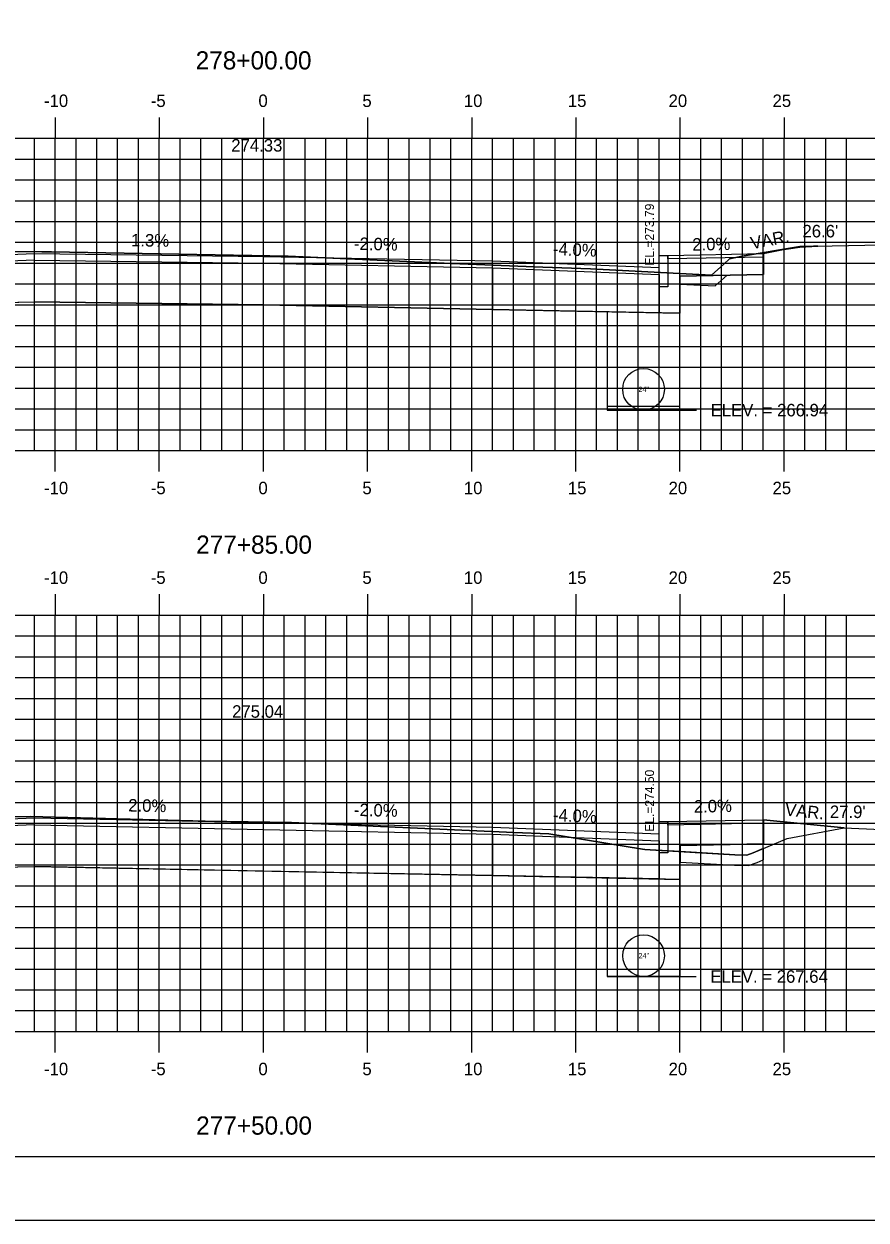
# Model space of a CAD drawing. Extents: x 854453 to 854623, y 366268 to 366378.
# Drawn here: x 854524.9 to 854565.4, y 366268.2 to 366325.6 of the extents above; entities that cross this region are included whole.
import ezdxf

# ---------------------------------------------------------------- set-up
doc = ezdxf.new("R2010")
doc.units = 0
for name, color, linetype in [('ANNOTATION', 7, 'Continuous'), ('BORDER', 7, 'Continuous'), ('D_Curb_Type_1_Rt', 7, 'Continuous'), ('D_Roadway_Centerline', 7, 'Continuous'), ('D_Roadway_Centerline_Text', 7, 'Continuous'), ('D_Roadway_Edge_Shoulder', 7, 'Continuous'), ('D_Roadway_Edge_TW', 7, 'Continuous'), ('D_Roadway_FinishedGrade', 7, 'Continuous'), ('D_Roadway_Sidewalks_Paved', 7, 'Continuous'), ('D_Roadway_SubGrade', 7, 'Continuous'), ('D_Text_Standard', 7, 'Continuous'), ('H_V ANNOTATION', 7, 'Continuous'), ('JUNK COM EXC', 7, 'Continuous'), ('JUNK FILL', 7, 'Continuous'), ('junk grubnfill', 7, 'Continuous'), ('junk strct exc', 7, 'Continuous'), ('MAJOR', 7, 'Continuous'), ('MINOR', 7, 'Continuous'), ('PDRAIN', 7, 'Continuous'), ('PLOT BOUNDARY', 7, 'Continuous'), ('S_Roadway_Centerline', 7, 'Continuous')]:
    doc.layers.add(name, color=color, linetype=linetype)

msp = doc.modelspace()

# ---------------------------------------------------------------- linework, layer by layer
at = {"layer": 'BORDER'}
msp.add_line((854461.439, 366271.236), (854621.439, 366271.236), dxfattribs=at)
at = {"layer": 'D_Curb_Type_1_Rt'}
for points in [[(854555.855, 366314.51), (854555.855, 366313.01), (854555.438, 366313.01), (854555.438, 366314.51)], [(854555.855, 366287.318), (854555.855, 366285.818), (854555.439, 366285.818), (854555.439, 366287.318)]]:
    msp.add_lwpolyline(points, close=True, dxfattribs=at)
at = {"layer": 'D_Roadway_Centerline'}
msp.add_lwpolyline([(854525.439, 366314.61), (854536.439, 366314.467), (854547.439, 366314.247)], dxfattribs=at)
at = {"layer": 'D_Roadway_Edge_Shoulder'}
msp.add_lwpolyline([(854517.439, 366314.29), (854525.439, 366314.61), (854536.439, 366314.467), (854547.439, 366314.247), (854555.434, 366313.927)], dxfattribs=at)
at = {"layer": 'D_Roadway_Edge_TW'}
msp.add_lwpolyline([(854517.439, 366287.174), (854525.439, 366287.494), (854547.439, 366287.054), (854555.434, 366286.734)], dxfattribs=at)
at = {"layer": 'D_Roadway_FinishedGrade'}
for p, q in [((854560.443, 366314.602), (854561.336, 366314.776)), ((854560.443, 366287.409), (854564.329, 366287.018))]:
    msp.add_line(p, q, dxfattribs=at)
msp.add_arc((854563.255, 366304.962), 10, 91.10922, 101.06432, dxfattribs=at)
at = {"layer": 'D_Roadway_Sidewalks_Paved'}
for points in [[(854555.855, 366314.51), (854560.443, 366314.602), (854560.443, 366314.435), (854555.855, 366314.344)], [(854555.855, 366287.317), (854560.443, 366287.409), (854560.443, 366287.242), (854555.855, 366287.151)]]:
    msp.add_lwpolyline(points, close=True, dxfattribs=at)
at = {"layer": 'D_Roadway_SubGrade'}
msp.add_line((854560.439, 366286.024), (854560.439, 366285.482), dxfattribs=at)
for points in [[(854560.443, 366314.435), (854560.443, 366313.602), (854556.439, 366313.522), (854556.439, 366311.733), (854555.439, 366311.753)], [(854556.439, 366313.136), (854558.125, 366313.047), (854558.712, 366313.567)], [(854555.442, 366284.561), (854556.442, 366284.541), (854556.442, 366286.163), (854560.444, 366286.242), (854560.444, 366287.242)], [(854556.442, 366285.373), (854559.06, 366285.219), (854559.733, 366285.207), (854560.14, 366285.357), (854560.439, 366285.482)]]:
    msp.add_lwpolyline(points, dxfattribs=at)
for points in [[(854525.439, 366314.276), (854517.439, 366313.956), (854517.439, 366312.116), (854525.439, 366312.276)], [(854525.439, 366312.276), (854525.439, 366314.276), (854536.439, 366314.133), (854547.439, 366313.913), (854547.439, 366311.913), (854536.439, 366312.133)], [(854547.439, 366313.913), (854555.439, 366313.593), (854555.439, 366311.753), (854547.439, 366311.913)], [(854525.439, 366287.161), (854517.439, 366286.841), (854517.439, 366285.001), (854525.439, 366285.161)], [(854525.439, 366285.161), (854525.439, 366287.161), (854536.439, 366286.941), (854547.439, 366286.721), (854547.439, 366284.721), (854536.439, 366284.941)], [(854547.439, 366286.721), (854555.438, 366286.401), (854555.438, 366284.561), (854547.439, 366284.721)]]:
    msp.add_lwpolyline(points, close=True, dxfattribs=at)
at = {"layer": 'D_Text_Standard'}
for points in [[(854556.439, 366307.081), (854556.552, 366307.081), (854557.232, 366307.081)], [(854556.442, 366279.876), (854556.536, 366279.876), (854557.216, 366279.876)]]:
    msp.add_lwpolyline(points, dxfattribs=at)
at = {"layer": 'JUNK COM EXC'}
for points in [[(854516.439, 366312.096), (854525.439, 366312.276), (854536.439, 366312.133), (854547.439, 366311.913), (854556.439, 366311.733), (854556.439, 366313.522), (854560.443, 366313.602), (854560.443, 366314.602), (854561.336, 366314.776), (854562.195, 366314.906), (854563.061, 366314.96), (854562.191, 366314.943), (854559.426, 366314.472), (854558.821, 366314.345), (854558.551, 366314.092), (854557.947, 366313.557), (854552.145, 366313.864), (854549.856, 366313.941), (854545.477, 366314.129), (854537.624, 366314.472), (854528.872, 366314.638), (854526.255, 366314.684), (854525.794, 366314.691), (854518.996, 366314.706)], [(854516.439, 366284.981), (854525.439, 366285.161), (854547.439, 366284.721), (854556.442, 366284.541), (854556.442, 366285.874), (854555.009, 366285.958), (854554.759, 366285.977), (854554.645, 366285.985), (854550.143, 366286.731), (854548.458, 366286.8), (854537.783, 366287.274), (854533.635, 366287.344), (854525.262, 366287.564), (854521.88, 366287.531)]]:
    msp.add_lwpolyline(points, dxfattribs=at)
at = {"layer": 'JUNK FILL'}
msp.add_lwpolyline([(854564.329, 366287.018), (854560.443, 366287.409), (854560.444, 366286.242), (854556.442, 366286.163), (854556.442, 366285.874), (854559.079, 366285.719), (854559.648, 366285.708), (854559.956, 366285.822), (854561.583, 366286.503)], close=True, dxfattribs=at)
at = {"layer": 'junk grubnfill'}
msp.add_lwpolyline([(854560.439, 366285.482), (854560.439, 366286.024), (854559.956, 366285.822), (854559.648, 366285.708), (854559.079, 366285.719), (854556.442, 366285.874), (854556.442, 366285.373), (854559.06, 366285.219), (854559.733, 366285.207), (854560.14, 366285.357), (854560.439, 366285.482)], dxfattribs=at)
at = {"layer": 'junk strct exc'}
for points in [[(854552.939, 366311.803), (854552.939, 366307.271), (854556.439, 366307.271), (854556.439, 366311.733)], [(854552.942, 366284.611), (854552.942, 366279.896), (854556.442, 366279.896), (854556.442, 366284.541)]]:
    msp.add_lwpolyline(points, close=True, dxfattribs=at)
at = {"layer": 'MAJOR'}
for p, q in [((854526.439, 366321.143), (854526.439, 366320.141)), ((854531.439, 366321.143), (854531.439, 366320.141)), ((854536.439, 366321.143), (854536.439, 366320.141)), ((854541.439, 366321.143), (854541.439, 366320.141)), ((854546.439, 366321.143), (854546.439, 366320.141)), ((854551.439, 366321.143), (854551.439, 366320.141)), ((854556.439, 366321.143), (854556.439, 366320.141)), ((854561.439, 366321.143), (854561.439, 366320.141)), ((854466.439, 366320.141), (854606.439, 366320.141)), ((854466.439, 366320.141), (854606.439, 366320.141)), ((854526.439, 366305.141), (854526.439, 366320.141)), ((854531.439, 366305.141), (854531.439, 366320.141)), ((854536.439, 366305.141), (854536.439, 366320.141)), ((854541.439, 366305.141), (854541.439, 366320.141)), ((854546.439, 366305.141), (854546.439, 366320.141)), ((854551.439, 366305.141), (854551.439, 366320.141)), ((854556.439, 366305.141), (854556.439, 366320.141)), ((854561.439, 366305.141), (854561.439, 366320.141)), ((854466.439, 366315.141), (854606.439, 366315.141)), ((854466.439, 366310.141), (854606.439, 366310.141)), ((854466.439, 366305.141), (854606.439, 366305.141)), ((854466.439, 366305.141), (854606.439, 366305.141)), ((854526.439, 366304.139), (854526.439, 366305.141)), ((854531.439, 366304.139), (854531.439, 366305.141)), ((854536.439, 366304.139), (854536.439, 366305.141)), ((854541.439, 366304.139), (854541.439, 366305.141)), ((854546.439, 366304.139), (854546.439, 366305.141)), ((854551.439, 366304.139), (854551.439, 366305.141)), ((854556.439, 366304.139), (854556.439, 366305.141)), ((854561.439, 366304.139), (854561.439, 366305.141)), ((854526.439, 366298.238), (854526.439, 366297.236)), ((854531.439, 366298.238), (854531.439, 366297.236)), ((854536.439, 366298.238), (854536.439, 366297.236)), ((854541.439, 366298.238), (854541.439, 366297.236)), ((854546.439, 366298.238), (854546.439, 366297.236)), ((854551.439, 366298.238), (854551.439, 366297.236)), ((854556.439, 366298.238), (854556.439, 366297.236)), ((854561.439, 366298.238), (854561.439, 366297.236)), ((854466.439, 366297.236), (854606.439, 366297.236)), ((854466.439, 366297.236), (854606.439, 366297.236)), ((854526.439, 366277.236), (854526.439, 366297.236)), ((854531.439, 366277.236), (854531.439, 366297.236)), ((854536.439, 366277.236), (854536.439, 366297.236)), ((854541.439, 366277.236), (854541.439, 366297.236)), ((854546.439, 366277.236), (854546.439, 366297.236)), ((854551.439, 366277.236), (854551.439, 366297.236)), ((854556.439, 366277.236), (854556.439, 366297.236)), ((854561.439, 366277.236), (854561.439, 366297.236)), ((854466.439, 366292.236), (854606.439, 366292.236)), ((854466.439, 366287.236), (854606.439, 366287.236)), ((854466.439, 366282.236), (854606.439, 366282.236)), ((854466.439, 366277.236), (854606.439, 366277.236)), ((854466.439, 366277.236), (854606.439, 366277.236)), ((854526.439, 366276.234), (854526.439, 366277.236)), ((854531.439, 366276.234), (854531.439, 366277.236)), ((854536.439, 366276.234), (854536.439, 366277.236)), ((854541.439, 366276.234), (854541.439, 366277.236)), ((854546.439, 366276.234), (854546.439, 366277.236)), ((854551.439, 366276.234), (854551.439, 366277.236)), ((854556.439, 366276.234), (854556.439, 366277.236)), ((854561.439, 366276.234), (854561.439, 366277.236))]:
    msp.add_line(p, q, dxfattribs=at)
at = {"layer": 'MINOR'}
for p, q in [((854525.439, 366305.141), (854525.439, 366320.141)), ((854527.439, 366305.141), (854527.439, 366320.141)), ((854528.439, 366305.141), (854528.439, 366320.141)), ((854529.439, 366305.141), (854529.439, 366320.141)), ((854530.439, 366305.141), (854530.439, 366320.141)), ((854532.439, 366305.141), (854532.439, 366320.141)), ((854533.439, 366305.141), (854533.439, 366320.141)), ((854534.439, 366305.141), (854534.439, 366320.141)), ((854535.439, 366305.141), (854535.439, 366320.141)), ((854537.439, 366305.141), (854537.439, 366320.141)), ((854538.439, 366305.141), (854538.439, 366320.141)), ((854539.439, 366305.141), (854539.439, 366320.141)), ((854540.439, 366305.141), (854540.439, 366320.141)), ((854542.439, 366305.141), (854542.439, 366320.141)), ((854543.439, 366305.141), (854543.439, 366320.141)), ((854544.439, 366305.141), (854544.439, 366320.141)), ((854545.439, 366305.141), (854545.439, 366320.141)), ((854547.439, 366305.141), (854547.439, 366320.141)), ((854548.439, 366305.141), (854548.439, 366320.141)), ((854549.439, 366305.141), (854549.439, 366320.141)), ((854550.439, 366305.141), (854550.439, 366320.141)), ((854552.439, 366305.141), (854552.439, 366320.141)), ((854553.439, 366305.141), (854553.439, 366320.141)), ((854554.439, 366305.141), (854554.439, 366320.141)), ((854555.439, 366305.141), (854555.439, 366320.141)), ((854557.439, 366305.141), (854557.439, 366320.141)), ((854558.439, 366305.141), (854558.439, 366320.141)), ((854559.439, 366305.141), (854559.439, 366320.141)), ((854560.439, 366305.141), (854560.439, 366320.141)), ((854562.439, 366305.141), (854562.439, 366320.141)), ((854563.439, 366305.141), (854563.439, 366320.141)), ((854564.439, 366305.141), (854564.439, 366320.141)), ((854466.439, 366319.141), (854606.439, 366319.141)), ((854466.439, 366318.141), (854606.439, 366318.141)), ((854466.439, 366317.141), (854606.439, 366317.141)), ((854466.439, 366316.141), (854606.439, 366316.141)), ((854466.439, 366314.141), (854606.439, 366314.141)), ((854466.439, 366313.141), (854606.439, 366313.141)), ((854466.439, 366312.141), (854606.439, 366312.141)), ((854466.439, 366311.141), (854606.439, 366311.141)), ((854466.439, 366309.141), (854606.439, 366309.141)), ((854466.439, 366308.141), (854606.439, 366308.141)), ((854466.439, 366307.141), (854606.439, 366307.141)), ((854466.439, 366306.141), (854606.439, 366306.141)), ((854525.439, 366277.236), (854525.439, 366297.236)), ((854527.439, 366277.236), (854527.439, 366297.236)), ((854528.439, 366277.236), (854528.439, 366297.236)), ((854529.439, 366277.236), (854529.439, 366297.236)), ((854530.439, 366277.236), (854530.439, 366297.236)), ((854532.439, 366277.236), (854532.439, 366297.236)), ((854533.439, 366277.236), (854533.439, 366297.236)), ((854534.439, 366277.236), (854534.439, 366297.236)), ((854535.439, 366277.236), (854535.439, 366297.236)), ((854537.439, 366277.236), (854537.439, 366297.236)), ((854538.439, 366277.236), (854538.439, 366297.236)), ((854539.439, 366277.236), (854539.439, 366297.236)), ((854540.439, 366277.236), (854540.439, 366297.236)), ((854542.439, 366277.236), (854542.439, 366297.236)), ((854543.439, 366277.236), (854543.439, 366297.236)), ((854544.439, 366277.236), (854544.439, 366297.236)), ((854545.439, 366277.236), (854545.439, 366297.236)), ((854547.439, 366277.236), (854547.439, 366297.236)), ((854548.439, 366277.236), (854548.439, 366297.236)), ((854549.439, 366277.236), (854549.439, 366297.236)), ((854550.439, 366277.236), (854550.439, 366297.236)), ((854552.439, 366277.236), (854552.439, 366297.236)), ((854553.439, 366277.236), (854553.439, 366297.236)), ((854554.439, 366277.236), (854554.439, 366297.236)), ((854555.439, 366277.236), (854555.439, 366297.236)), ((854557.439, 366277.236), (854557.439, 366297.236)), ((854558.439, 366277.236), (854558.439, 366297.236)), ((854559.439, 366277.236), (854559.439, 366297.236)), ((854560.439, 366277.236), (854560.439, 366297.236)), ((854562.439, 366277.236), (854562.439, 366297.236)), ((854563.439, 366277.236), (854563.439, 366297.236)), ((854564.439, 366277.236), (854564.439, 366297.236)), ((854466.439, 366296.236), (854606.439, 366296.236)), ((854466.439, 366295.236), (854606.439, 366295.236)), ((854466.439, 366294.236), (854606.439, 366294.236)), ((854466.439, 366293.236), (854606.439, 366293.236)), ((854466.439, 366291.236), (854606.439, 366291.236)), ((854466.439, 366290.236), (854606.439, 366290.236)), ((854466.439, 366289.236), (854606.439, 366289.236)), ((854466.439, 366288.236), (854606.439, 366288.236)), ((854466.439, 366286.236), (854606.439, 366286.236)), ((854466.439, 366285.236), (854606.439, 366285.236)), ((854466.439, 366284.236), (854606.439, 366284.236)), ((854466.439, 366283.236), (854606.439, 366283.236)), ((854466.439, 366281.236), (854606.439, 366281.236)), ((854466.439, 366280.236), (854606.439, 366280.236)), ((854466.439, 366279.236), (854606.439, 366279.236)), ((854466.439, 366278.236), (854606.439, 366278.236))]:
    msp.add_line(p, q, dxfattribs=at)
at = {"layer": 'PDRAIN'}
for points in [[(854552.939, 366311.803), (854552.939, 366307.081), (854556.439, 366307.081), (854556.439, 366311.733)], [(854552.942, 366284.611), (854552.942, 366279.876), (854556.442, 366279.876), (854556.442, 366284.541)]]:
    msp.add_lwpolyline(points, dxfattribs=at)
for centre in [(854554.689, 366308.081), (854554.692, 366280.876)]:
    msp.add_circle(centre, 1, dxfattribs=at)
at = {"layer": 'PLOT BOUNDARY'}
msp.add_lwpolyline([(854453.345, 366268.177), (854623.345, 366268.177), (854623.345, 366378.177), (854453.345, 366378.177)], close=True, dxfattribs=at)
at = {"layer": 'S_Roadway_Centerline'}
for points in [[(854518.996, 366314.706), (854525.794, 366314.691), (854526.255, 366314.684), (854528.872, 366314.638), (854537.624, 366314.472), (854545.477, 366314.129), (854549.856, 366313.941), (854552.145, 366313.864), (854557.947, 366313.557), (854558.551, 366314.092), (854558.821, 366314.345), (854559.426, 366314.472), (854562.191, 366314.943), (854567.654, 366315.049)], [(854521.88, 366287.531), (854525.262, 366287.564), (854533.635, 366287.344), (854537.783, 366287.274), (854548.458, 366286.8), (854550.143, 366286.731), (854554.645, 366285.985), (854554.759, 366285.977), (854555.009, 366285.958), (854559.079, 366285.719), (854559.648, 366285.708), (854559.956, 366285.822), (854561.583, 366286.503), (854564.329, 366287.018), (854567.532, 366286.879)]]:
    msp.add_lwpolyline(points, dxfattribs=at)

# ---------------------------------------------------------------- texts
at = {"layer": 'ANNOTATION'}
for s, rotation, p in [('1.3%', 359.2552, (854530.08, 366314.949)), ('VAR.', 11.06432, (854559.891, 366314.799)), ('-2.0%', 358.85424, (854540.782, 366314.78)), ('-4.0%', 357.70949, (854550.332, 366314.532)), ('2.0%', 1.14563, (854557.035, 366314.738)), ('2.0%', 358.85424, (854529.942, 366287.805)), ('-2.0%', 358.85424, (854540.782, 366287.588)), ('-4.0%', 357.70947, (854550.334, 366287.339)), ('2.0%', 1.14881, (854557.109, 366287.743)), ('VAR.', 354.25391, (854561.463, 366287.608))]:
    msp.add_text(s, height=0.6, rotation=rotation, dxfattribs=at).set_placement(p)
at = {"layer": 'D_Roadway_Centerline_Text'}
for s, p in [('274.33', (854534.895, 366319.499)), ('275.04', (854534.935, 366292.306))]:
    msp.add_text(s, height=0.6, dxfattribs=at).set_placement(p)
at = {"layer": 'D_Text_Standard'}
for s, p in [(' EL.=273.79', (854555.193, 366313.858)), (' EL.=274.50', (854555.193, 366286.666))]:
    msp.add_text(s, height=0.4335, rotation=90, dxfattribs=at).set_placement(p)
for s, p in [("26.6'", (854562.321, 366315.378)), ('ELEV. = 266.94', (854557.912, 366306.781)), ("27.9'", (854563.638, 366287.488)), ('ELEV. = 267.64', (854557.896, 366279.576))]:
    msp.add_text(s, height=0.6, dxfattribs=at).set_placement(p)
at = {"layer": 'H_V ANNOTATION'}
for s, height, p in [('278+00.00', 0.875, (854533.184, 366323.444)), ('-10', 0.6, (854525.903, 366321.641)), ('-5', 0.6, (854531.029, 366321.641)), ('0', 0.6, (854536.198, 366321.641)), ('5', 0.6, (854541.19, 366321.641)), ('10', 0.6, (854546.064, 366321.641)), ('15', 0.6, (854551.056, 366321.641)), ('20', 0.6, (854555.893, 366321.641)), ('25', 0.6, (854560.885, 366321.641)), ('-10', 0.6, (854525.903, 366303.041)), ('-5', 0.6, (854531.029, 366303.041)), ('0', 0.6, (854536.198, 366303.041)), ('5', 0.6, (854541.19, 366303.041)), ('10', 0.6, (854546.064, 366303.041)), ('15', 0.6, (854551.056, 366303.041)), ('20', 0.6, (854555.893, 366303.041)), ('25', 0.6, (854560.885, 366303.041)), ('277+85.00', 0.875, (854533.208, 366300.184)), ('-10', 0.6, (854525.903, 366298.736)), ('-5', 0.6, (854531.029, 366298.736)), ('0', 0.6, (854536.198, 366298.736)), ('5', 0.6, (854541.19, 366298.736)), ('10', 0.6, (854546.064, 366298.736)), ('15', 0.6, (854551.056, 366298.736)), ('20', 0.6, (854555.893, 366298.736)), ('25', 0.6, (854560.885, 366298.736)), ('-10', 0.6, (854525.903, 366275.136)), ('-5', 0.6, (854531.029, 366275.136)), ('0', 0.6, (854536.198, 366275.136)), ('5', 0.6, (854541.19, 366275.136)), ('10', 0.6, (854546.064, 366275.136)), ('15', 0.6, (854551.056, 366275.136)), ('20', 0.6, (854555.893, 366275.136)), ('25', 0.6, (854560.885, 366275.136)), ('277+50.00', 0.875, (854533.208, 366272.28))]:
    msp.add_text(s, height=height, dxfattribs=at).set_placement(p)
at = {"layer": 'PDRAIN'}
for p in [(854554.447, 366307.956), (854554.45, 366280.751)]:
    msp.add_text('24"', height=0.25, dxfattribs=at).set_placement(p)
at = {"layer": 'S_Roadway_Centerline'}
for s, p in [('C', (854537.619, 366314.472)), ('L', (854537.624, 366314.465)), ('C', (854537.778, 366287.274)), ('L', (854537.783, 366287.267))]:
    msp.add_text(s, height=0.0146, dxfattribs=at).set_placement(p)

doc.saveas('drawing.dxf')
